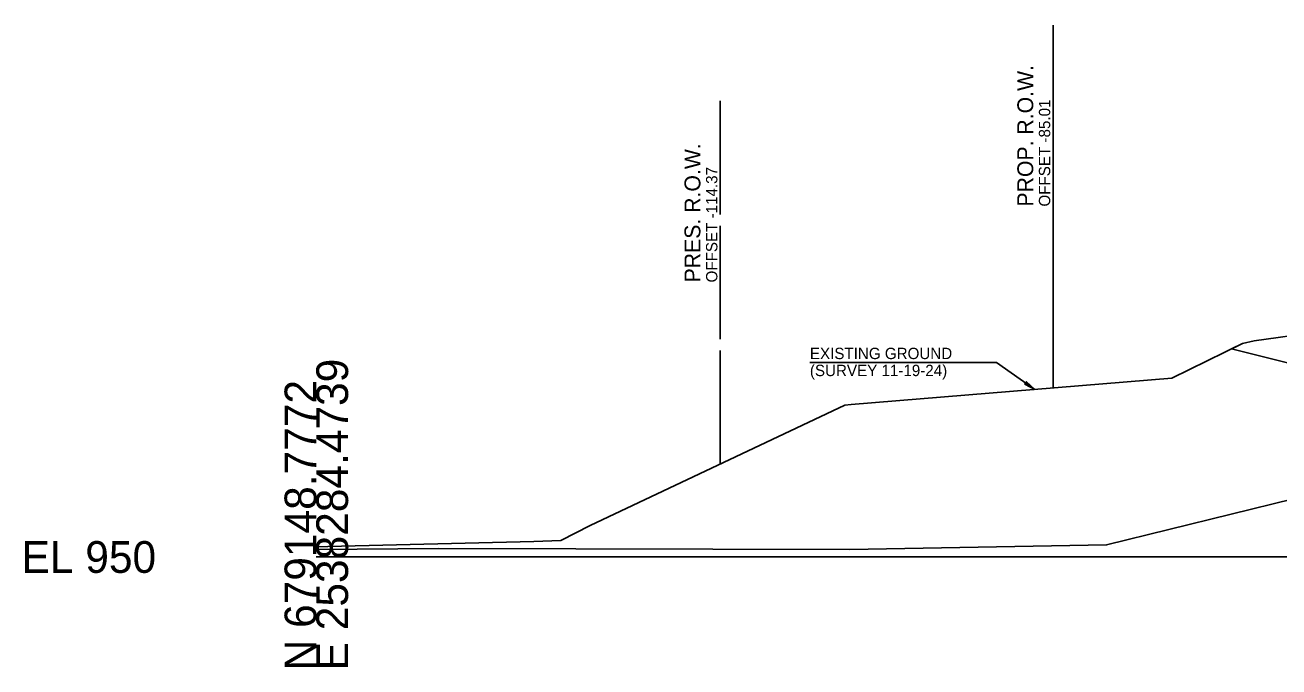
# Model space of a CAD drawing. Extents: x -26 to 1603, y -30 to 14537.
# Drawn here: x -25.7 to 84.9, y 3490.3 to 3546.9 of the extents above; entities that cross this region are included whole.
import ezdxf

# ---------------------------------------------------------------- set-up
doc = ezdxf.new("R2010")
doc.units = 0
for name, color, linetype in [('DESIGN - ROW - Right-of-Way and Easement Labels', 7, 'Continuous'), ('DESIGN - ROW - Right-of-Way Linework', 7, 'Continuous'), ('DESIGN - SCRATCH - User 999 - Unsuitable Earthwork', 7, 'Continuous'), ('DESIGN - SHEET - Light Grid', 7, 'Continuous'), ('SURVEY - GROUND - Top of Ground', 7, 'Continuous'), ('SURVEY - PROPERTY - ROW Lines', 7, 'Continuous'), ('SURVEY - PROPERTY - ROW Lines Text', 7, 'Continuous')]:
    doc.layers.add(name, color=color, linetype=linetype)

msp = doc.modelspace()

# ---------------------------------------------------------------- linework, layer by layer
at = {"layer": 'DESIGN - ROW - Right-of-Way Linework'}
msp.add_line((64.99, 3514.9), (64.99, 3546.9), dxfattribs=at)
at = {"layer": 'DESIGN - SCRATCH - User 999 - Unsuitable Earthwork'}
msp.add_lwpolyline([(109.04, 3511.28), (80.74, 3518.35), (81.69, 3518.82), (82.74, 3519.05), (93.72, 3520.58)], dxfattribs=at)
at = {"layer": 'DESIGN - SHEET - Light Grid'}
msp.add_line((0, 3500), (150, 3500), dxfattribs=at)
at = {"layer": 'SURVEY - GROUND - Top of Ground'}
for p in [(43.54, 3517.16), (63.39, 3514.77)]:
    msp.add_line(p, (60.01, 3517.16), dxfattribs=at)
for points in [[(0, 3500.89), (1.01, 3500.92), (19.19, 3501.37), (21.57, 3501.44), (24.15, 3502.79), (46.62, 3513.4), (47.17, 3513.44), (75.47, 3515.76), (81.69, 3518.82), (82.74, 3519.05), (93.72, 3520.58)], [(0, 3500.65), (10.82, 3500.76), (47.05, 3500.65), (69.71, 3501.07), (86.19, 3505.13), (122.45, 3514.89), (128.17, 3516.28), (129.02, 3516.53), (129.98, 3516.67), (131.52, 3516.86), (150, 3517.26), (180.35, 3517.92), (193.38, 3518.13), (228.69, 3518.91), (236.9, 3519.1), (279.15, 3519.95), (280.47, 3519.96), (300, 3519.59)], [(63.39, 3514.77), (62.5, 3515.25), (62.67, 3515.28), (62.64, 3515.46), (63.39, 3514.77)]]:
    msp.add_lwpolyline(points, dxfattribs=at)
msp.add_lwpolyline([(63.39, 3514.77), (62.5, 3515.25), (62.67, 3515.28), (62.64, 3515.46)], close=True, dxfattribs=at)
at = {"layer": 'SURVEY - PROPERTY - ROW Lines'}
for p, q in [((35.63, 3530.21), (35.63, 3540.21)), ((35.63, 3519.21), (35.63, 3529.21)), ((35.63, 3508.21), (35.63, 3518.21))]:
    msp.add_line(p, q, dxfattribs=at)

# ---------------------------------------------------------------- texts
at = {"layer": 'DESIGN - ROW - Right-of-Way and Easement Labels'}
for s, height, p in [('PROP. R.O.W.', 1.4, (63.24, 3530.9)), ('OFFSET -85.01', 1, (64.74, 3530.9))]:
    msp.add_text(s, height=height, rotation=90, dxfattribs=at).set_placement(p)
at = {"layer": 'DESIGN - SHEET - Light Grid'}
for s, p in [('E 2538284.4739', (2.8, 3490)), ('N 679148.7772', (0, 3490))]:
    msp.add_text(s, height=2.8, rotation=90, dxfattribs=at).set_placement(p)
msp.add_text('EL 950', height=2.8, dxfattribs=at).set_placement((-26, 3498.6))
at = {"layer": 'SURVEY - GROUND - Top of Ground'}
for s, p in [('EXISTING GROUND', (43.54, 3517.45)), ('(SURVEY 11-19-24)', (43.54, 3515.95))]:
    msp.add_text(s, height=1, dxfattribs=at).set_placement(p)
at = {"layer": 'SURVEY - PROPERTY - ROW Lines Text'}
for s, height, p in [('PRES. R.O.W.', 1.4, (33.88, 3524.21)), ('OFFSET -114.37', 1, (35.38, 3524.21))]:
    msp.add_text(s, height=height, rotation=90, dxfattribs=at).set_placement(p)

doc.saveas('drawing.dxf')
